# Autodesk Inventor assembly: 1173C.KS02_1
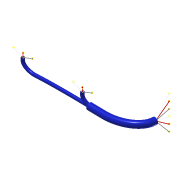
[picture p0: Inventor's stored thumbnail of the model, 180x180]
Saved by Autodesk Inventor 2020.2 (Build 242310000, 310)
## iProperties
Part Number: 1173C.KS02_1
Material: Ogólne
Description: 1173C
Part Number: 1173C.KS01_1
ParentFileIdentifier: 5|1|0|0|62|1|0|0|80|0|65|0|84|0|72|0|83|0|59|0|67|0|58|0|92|0|90|0|98|0|105|0|243|0|114|0|32|0|7|1|119|0|105|0|99|0|122|0|101|0|68|1|32|0|65|0|73|0|32|0|50|0|48
Manager: www.cadconsulting.pl
Company: Fabian Stasiak CAD Consulting
Created: 2014-09
Part Number: W_200_01_P2.Wiązka przewodów1
Document SubType Name: Assembly
Designer: F.Stasiak
Catalog Web Link: www.expertbooks.pl
HarnessSettings: <HarnessSettings><Defaults><Segments><Diameter value="0.200 in" fromwires="True"/><Offset value="0.100 in"/><ColorStyle value="Niebieska - farba ścienna - lśnią
Author: F.Stasiak
Subject: Zbiór ćwiczeń. Autodesk Inventor 2020. Kurs Professional
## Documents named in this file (2)
- C:\2020_Kurs_Professional\R2 Wiązki\W_200_01_P2\AIP\przewody i wiązki przewodów\W_200_01_P2.Wiązka przewodów1.iam
- C:\2020_Kurs_Professional\R2 Wiązki\W_200_01_P2\AIP\przewody i wiązki przewodów\W_200_01_P2.Wiązka przewodów1.ipt
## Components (3 placed, 3 different names)
1. Wiązka przewodów1
2. HA_VC_135:1
3. HA_VC_145:1
